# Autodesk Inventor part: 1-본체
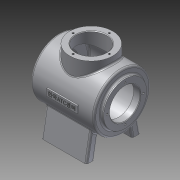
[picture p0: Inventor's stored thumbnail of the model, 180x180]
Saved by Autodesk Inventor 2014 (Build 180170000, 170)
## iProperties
Created: 2015-01
Part Number: 1-본체
Material: Aluminum 6061
Document SubType Name: Modeling
Designer: user
Density: 2.71 g/cm^3
Appearance: Aluminum - Flat
Mass: 1023.02 g
Surface Area: 1061.45 cm^2
Volume: 377.498 cm^3
Author: user
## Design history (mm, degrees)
sketch "Sketch1"
  geometry: C1 r 50 at (0, 0); 1 further point
  constraints: 1 centre point, 1 coincident
  dimensions: "d0" = 100 diameter of C1
extrude "Extrusion1" new body sketch "Sketch1" distance "d1" = 112; taper "d2" = 0 deg
sketch "Sketch2"
  geometry: C1 r 50 at (0, 0) reference; C2 r 38 at (0, 0)
  constraints: 1 centre point, 1 coincident
  dimensions: "d3" = 76 diameter of C2
extrude "Extrusion2" join sketch "Sketch2" distance "d4" = 5; taper "d5" = 0 deg
sketch "Sketch3"
  geometry: C1 r 50 at (0, 0) reference; C2 r 38 at (0, 0)
  constraints: 1 centre point, 1 coincident
  dimensions: "d6" = 76 diameter of C2
extrude "Extrusion3" join sketch "Sketch3" distance "d7" = 5; taper "d8" = 0 deg
workplane "Work Plane1"
sketch "Sketch4"
  geometry: C1 r 45 at (0, 0); 1 further point
  constraints: 1 centre point, 1 coincident
  dimensions: "d10" = 90 diameter of C1
extrude "Extrusion4" cut sketch "Sketch4" distance "d11" = 97; taper "d12" = 0 deg
workplane "Work Plane2"
workplane "Work Plane3"
sketch "Sketch5"
  geometry: L1 (0, 0)-(0, -80); L2 (33.5, -80)-(47.5, -80); L3 (47.5, -80)-(38.927, -31.38); L4 (47.5, -80)-(128.734, -80); L5 (33.5, -80)-(26.833, -42.19); L6 (-47.5, -80)-(-38.927, -31.38); L7 (-33.5, -80)-(-26.833, -42.19); L8 (-33.5, -80)-(-47.5, -80); A1 r 50 centre (0, 0) between (26.833, -42.19) and (38.927, -31.38) reference; A2 r 50 centre (0, 0) between (26.833, -42.19) and (38.927, -31.38); A3 r 50 centre (0, 0) between (-26.833, -42.19) and (-38.927, -31.38); 1 further point
  constraints: 16 end point, 6 point on circle, 4 symmetric about line, 2 centre point, 1 coincident, 1 horizontal, 1 parallel, 1 perpendicular, 1 vertical, 1 other
  dimensions: "d15" = 80 distance of L1.start L1.end; "d16" = 47.5 distance of L1.end L2.end; "d17" = 100 deg angle of L4 L3; "d101" = 14 distance of L2.end L2.start
extrude "Extrusion5" join sketch "Sketch5" distance "d19" = 80; taper "d20" = 0 deg
sketch "Sketch6"
  geometry: C1 r 38 at (0, 0) reference; C2 r 27 at (0, 0)
  constraints: 1 centre point, 1 coincident
  dimensions: "d21" = 54 diameter of C2
hole "Hole1" sketch "Sketch6" at (0, 0) diameter "d22" = 54; stored, may be unused: countersink angle "d26" = 90 deg, drill point angle "d28" = 118 deg; dims "d23" = 6, "d24" = 4, "d25" = 2, "d27" = 8
sketch "Sketch7" dims "d29" = 64
  geometry: C1 r 38 at (0, 0) reference; C2 r 4.365 at (0, 32); 1 further point
  constraints: 1 centre point, 1 coincident, 1 vertical alignment, 2 other
hole "Hole2" sketch "Sketch7" at (0, 32) diameter "d30" = 3.242; stored, may be unused: countersink angle "d34" = 90 deg, drill point angle "d36" = 118 deg; dims "d31" = 8, "d32" = 4, "d33" = 2, "d35" = 10
workaxis "Work Axis1"
pattern_circular "Circular Pattern1" dims angle "d38" = 360 deg
workplane "Work Plane4"
mirror "Mirror1"
workplane "Work Plane6"
sketch "Sketch9"
  geometry: L1 (-50, 0)-(50, 0) reference; L2 (50, 112)-(-50, 112) reference; L3 (-38, -5)-(38, -5) reference; L4 (0, -5)-(0, 57); L5 (38, 117)-(-38, 117) reference; C1 r 38 at (0, 57); 1 further point
  constraints: 2 end point, 1 centre point, 1 coincident, 1 midpoint, 1 perpendicular
  dimensions: "d62" = 62 distance of L4.start L4.end; "d63" = 76 diameter of C1
extrude "Extrusion6" join sketch "Sketch9" distance "d46" = 40; taper "d47" = 0 deg
sketch "Sketch12" dims "d64" = 64
  geometry: C1 r 38 at (0, 0) reference; C2 r 7.426 at (0, 32); 2 further points
  constraints: 1 centre point, 1 coincident, 1 vertical alignment, 2 other
hole "Hole4" sketch "Sketch12" at (0, 32) diameter "d65" = 3.242; stored, may be unused: countersink angle "d69" = 90 deg, drill point angle "d71" = 118 deg; dims "d66" = 8, "d67" = 4, "d68" = 2, "d70" = 10
sketch "Sketch13"
  geometry: C1 r 38 at (0, 0) reference; C2 r 27 at (0, 0); 1 further point
  constraints: 1 centre point, 1 coincident
  dimensions: "d72" = 54 diameter of C2
extrude "Extrusion8" cut sketch "Sketch13" distance "d73" = 40; taper "d74" = 0 deg
pattern_circular "Circular Pattern3" dims angle "d76" = 360 deg
sketch "Sketch14"
  geometry: L1 (-45, 8)-(45, 8) reference; L2 (-45, 105)-(45, 105) reference; L3 (0, 105)-(0, 8); L4 (0, 8)-(45, 8); L5 (45, 8)-(45, 105); L6 (45, 105)-(0, 105); 2 further points
  constraints: 8 end point, 2 midpoint, 2 perpendicular, 1 other
revolve "Revolution1" sketch "Sketch14" stored, may be unused: angle "d78" = 90 deg
workplane "Work Plane10"
sketch "Sketch15"
  geometry: L1 (106.411, 62)-(182.411, 62) reference; L2 (82.411, 38)-(82.411, -38) reference; L3 (117.411, 6)-(171.411, 6); L4 (171.411, 6)-(171.411, -6); L5 (171.411, -6)-(117.411, -6); L6 (117.411, -6)-(117.411, 6); 1 further point
  constraints: 8 end point, 2 parallel, 1 horizontal, 1 perpendicular
  dimensions: "d82" = 54 distance of L4.end L5.end; "d83" = 12 distance of L3.end L4.end
extrude "Extrusion9" join sketch "Sketch15" stored distance "d84" = 4; taper "d85" = 0 deg
sketch "Sketch16"
  geometry: L1 (119.524, 3.602)-(169.299, 3.602); L2 (169.299, 3.602)-(169.299, -3.602); L3 (169.299, -3.602)-(119.524, -3.602); L4 (119.524, -3.602)-(119.524, 3.602); 1 further point
  constraints: 2 other
emboss "Emboss1" sketch "Sketch16" dims "d0" = 100, "d10" = 90, "d86" = 0.5, "d87" = 0
fillet "Fillet1" dims "d88" = 3
fillet "Fillet2" dims "d89" = 3
fillet "Fillet3" dims "d90" = 3
fillet "Fillet4" dims "d91" = 3
fillet "Fillet5" dims "d92" = 3
fillet "Fillet6" dims "d93" = 3
fillet "Fillet7" dims "d94" = 3
chamfer "Chamfer1" distance "d95" = 1; stored, may be unused: second distance "d96" = 2, angle "d97" = 45 deg
chamfer "Chamfer2" distance "d98" = 1; stored, may be unused: second distance "d99" = 2, angle "d100" = 45 deg
body "Solid1"
node "Projected Loop1"
other parameters: "d9" = -7, "d13" = 0, "d14" = -21, "d40" = -56
